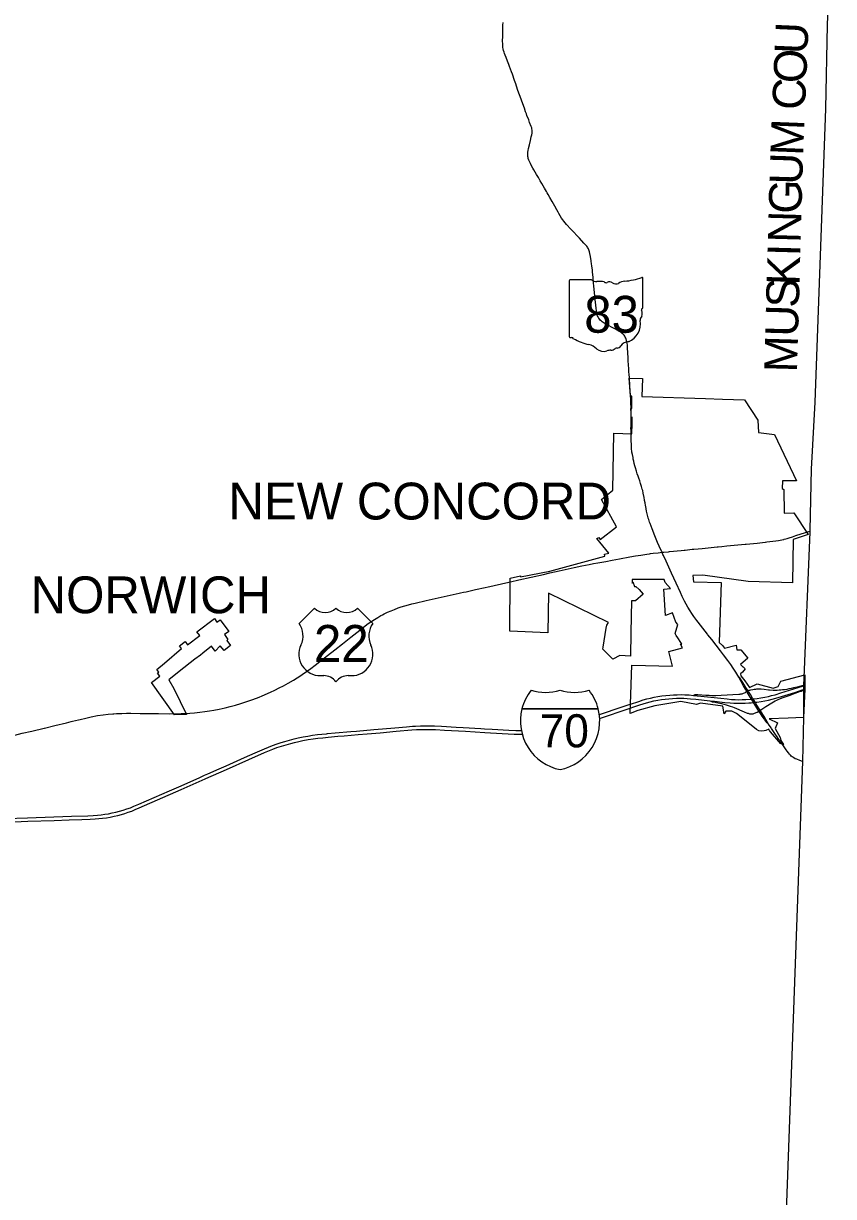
# Model space of a CAD drawing. Extents: x 2015843 to 2287843, y 623733 to 799733.
# Drawn here: x 2176633 to 2201296, y 702171 to 737859 of the extents above; entities that cross this region are included whole.
import ezdxf

# ---------------------------------------------------------------- set-up
doc = ezdxf.new("R2010")
doc.units = 0
for name, color, linetype in [('GM_X_Corporation', 7, 'Continuous'), ('GM_X_Corporation_Text', 7, 'Continuous'), ('GM_X_County', 7, 'Continuous'), ('GM_X_County_Text', 7, 'Continuous'), ('GM_X_Interstate_Location', 7, 'Continuous'), ('GM_X_Interstate_Shield', 7, 'Continuous'), ('GM_X_State_Location', 7, 'Continuous'), ('GM_X_State_Route', 7, 'Continuous'), ('GM_X_State_Shield', 7, 'Continuous'), ('GM_X_US_Location', 7, 'Continuous'), ('GM_X_US_Route', 7, 'Continuous'), ('GM_X_US_Shield', 7, 'Continuous'), ('UT_P_Electric', 7, 'Continuous')]:
    doc.layers.add(name, color=color, linetype=linetype)

msp = doc.modelspace()

# ---------------------------------------------------------------- linework, layer by layer
at = {"layer": 'GM_X_Corporation'}
for points in [[(2191451, 720987), (2191762, 721058), (2191762, 721027), (2192653, 721199), (2194328, 721649), (2194320, 721716), (2194451, 721742), (2194092, 722189), (2194145, 722225), (2194194, 722159), (2194685, 722548), (2194232, 723373), (2194577, 723661), (2194610, 725393), (2195151, 725377), (2195160, 725683), (2195160, 725881), (2195131, 725872), (2195131, 726003), (2195128, 726141), (2195158, 726147), (2195151, 726525), (2195115, 726526), (2195078, 727073), (2195482, 727063), (2195463, 726515), (2197399, 726451), (2197917, 726427), (2198585, 726406), (2198993, 725793), (2199006, 725418), (2199494, 725355), (2200168, 723940), (2199738, 723944), (2199736, 723714), (2199777, 723686), (2199793, 722961), (2200091, 722968), (2200524, 722309), (2200068, 722158), (2200042, 720846), (2198692, 720884), (2197317, 721070), (2197014, 721065), (2197034, 720876), (2197874, 720847), (2197844, 719945), (2197813, 719023), (2197913, 718936), (2197978, 718850), (2198329, 718949), (2198354, 718807), (2198473, 718808), (2198682, 718553), (2198465, 718356), (2198535, 718281), (2198543, 718289), (2198608, 718223), (2198526, 718126), (2198459, 718077), (2198472, 718010), (2198599, 717860), (2198732, 717653), (2198966, 717771), (2199456, 717636), (2199614, 717690), (2199695, 717849), (2200426, 718042), (2200422, 717725), (2200419, 717611), (2200385, 716743), (2199911, 716726), (2199334, 716706), (2199594, 716584), (2199517, 716406), (2199666, 716134), (2199693, 716043), (2199772, 715928), (2199748, 715912), (2199716, 715959), (2199687, 715946), (2199371, 716308), (2199350, 716344), (2199321, 716385), (2199234, 716349), (2199180, 716335), (2199115, 716328), (2199023, 716335), (2198952, 716375), (2198783, 716516), (2198341, 716868), (2198195, 716934), (2198021, 716934), (2197966, 716859), (2197925, 717087), (2197246, 717178), (2197125, 717140), (2196651, 717235), (2195856, 717098), (2195333, 716961), (2195106, 716866), (2195116, 717154), (2195158, 718339), (2196397, 718311), (2196276, 718752), (2196701, 718866), (2196639, 718972), (2196673, 718976), (2196648, 719025), (2196556, 719171), (2196505, 719239), (2196470, 719303), (2196550, 719570), (2196495, 719644), (2196392, 719925), (2196180, 719848), (2196124, 720653), (2196328, 720668), (2196171, 720856), (2196142, 720944), (2195168, 720942), (2195166, 720836), (2195189, 720871), (2195240, 720729), (2195272, 720731), (2195374, 720641), (2195497, 720494), (2195261, 720290), (2195147, 720294), (2195128, 719333), (2195109, 718606), (2194793, 718629), (2194572, 718517), (2194269, 718821), (2194283, 718884), (2194369, 719462), (2194398, 719550), (2194442, 719633), (2192618, 720528), (2192594, 719325), (2191441, 719368)], [(2180536, 717807), (2180787, 718002), (2180715, 718095), (2180755, 718125), (2180698, 718202), (2180922, 718401), (2181445, 718839), (2181383, 718927), (2181552, 719053), (2181630, 718960), (2181998, 719238), (2181914, 719352), (2182449, 719752), (2182522, 719647), (2182625, 719716), (2182890, 719366), (2182751, 719266), (2182859, 719118), (2182821, 719089), (2182936, 718935), (2182740, 718778), (2182622, 718928), (2182467, 718766), (2182355, 718914), (2182098, 718701), (2182018, 718642), (2181854, 718524), (2181374, 718148), (2181054, 717890), (2181214, 717626), (2181601, 716835), (2181232, 716830)]]:
    msp.add_lwpolyline(points, close=True, dxfattribs=at)
at = {"layer": 'GM_X_County'}
msp.add_lwpolyline([(2201296, 742683), (2201102, 737817), (2201047, 735259), (2200727, 726337), (2200609, 724295), (2200576, 722439), (2200575, 722396), (2200380, 717712), (2200376, 717595), (2200385, 716743), (2200352, 715403), (2199774, 699473)], dxfattribs=at)
at = {"layer": 'GM_X_Interstate_Shield'}
for p, q in [((2191808, 717007), (2194131, 717007)), ((2194131, 717007), (2191808, 717007)), ((2194131, 717007), (2191808, 717007))]:
    msp.add_line(p, q, dxfattribs=at)
for centre, start, end in [((2193272, 716637), 141.669, 165.8066), ((2192529, 719016), 253.0091, 286.9909), ((2193411, 719016), 253.0091, 286.9909), ((2192668, 716637), 14.1934, 38.331), ((2193272, 716637), 165.8066, 258.463), ((2192668, 716637), 281.537, 14.1934)]:
    msp.add_arc(centre, 1509, start, end, dxfattribs=at)
at = {"layer": 'GM_X_State_Route'}
msp.add_line((2195135, 725818), (2195136, 725870), dxfattribs=at)
for points in [[(2195030, 727819), (2195029, 727840), (2195023, 727987), (2195021, 728016), (2195018, 728069), (2195011, 728134), (2195006, 728166), (2194995, 728213), (2194980, 728260), (2194968, 728290), (2194954, 728319), (2194937, 728347), (2194918, 728373), (2194897, 728397), (2194873, 728419), (2194836, 728450), (2194795, 728477), (2194725, 728519), (2194619, 728575), (2194595, 728588), (2194406, 728688), (2194335, 728728), (2194279, 728763), (2194252, 728782), (2194226, 728803), (2194202, 728826), (2194180, 728851), (2194170, 728864), (2194151, 728891), (2194142, 728905), (2194126, 728934), (2194113, 728965), (2194103, 728996), (2194094, 729028), (2194087, 729060), (2194078, 729108), (2194076, 729124), (2194069, 729189), (2194057, 729302), (2194049, 729367), (2193998, 729872), (2193990, 729969), (2193977, 730116), (2193966, 730230), (2193961, 730279), (2193952, 730360), (2193937, 730473), (2193933, 730500), (2193928, 730538), (2193914, 730636), (2193896, 730766), (2193880, 730862), (2193869, 730910), (2193860, 730941), (2193849, 730972), (2193835, 731001), (2193819, 731029), (2193802, 731056), (2193782, 731082), (2193762, 731107), (2193696, 731180), (2193561, 731324), (2193506, 731383), (2193359, 731538), (2193302, 731597), (2193169, 731742), (2193126, 731791), (2193084, 731842), (2193054, 731881), (2193017, 731935), (2192974, 732005), (2192933, 732076), (2192909, 732119), (2192869, 732190), (2192806, 732304), (2192726, 732447), (2192661, 732561), (2192604, 732660), (2192579, 732703), (2192555, 732745), (2192498, 732844), (2192417, 732986), (2192368, 733071), (2192310, 733170), (2192252, 733269), (2192169, 733409), (2192144, 733452), (2192104, 733523), (2192065, 733595), (2192037, 733655), (2192018, 733700), (2192002, 733747), (2191994, 733780), (2191989, 733812), (2191987, 733846), (2191988, 733895), (2191992, 733944), (2191998, 733993), (2192011, 734058), (2192036, 734170), (2192067, 734298), (2192094, 734409), (2192109, 734473), (2192117, 734521), (2192121, 734553), (2192122, 734586), (2192120, 734618), (2192115, 734650), (2192107, 734681), (2192091, 734727), (2192043, 734849), (2192014, 734926), (2191961, 735063), (2191943, 735109), (2191920, 735170), (2191882, 735278), (2191832, 735417), (2191755, 735633), (2191716, 735741), (2191678, 735849), (2191619, 736020), (2191582, 736128), (2191517, 736314), (2191489, 736391), (2191434, 736545), (2191412, 736606), (2191372, 736714), (2191329, 736820), (2191297, 736896), (2191279, 736942), (2191264, 736988), (2191250, 737036), (2191239, 737084), (2191231, 737133), (2191225, 737182), (2191223, 737231), (2191222, 737330), (2191224, 737461), (2191224, 737526), (2191224, 737640), (2191226, 737722), (2191229, 737803), (2191235, 737885)], [(2195068, 727239), (2195060, 727350), (2195045, 727595), (2195041, 727660), (2195038, 727709), (2195030, 727819)], [(2195134, 726133), (2195127, 726346), (2195120, 726461), (2195117, 726506), (2195116, 726523), (2195114, 726557), (2195105, 726680), (2195094, 726844), (2195079, 727070), (2195070, 727202), (2195068, 727239)], [(2195136, 725870), (2195136, 726002), (2195134, 726133)], [(2195130, 725391), (2195130, 725423), (2195130, 725480), (2195129, 725545), (2195130, 725593), (2195132, 725691), (2195133, 725723), (2195135, 725818)], [(2195264, 724343), (2195248, 724396), (2195226, 724475), (2195211, 724539), (2195199, 724604), (2195190, 724652), (2195171, 724748), (2195158, 724813), (2195154, 724845), (2195148, 724910), (2195146, 724942), (2195141, 725057), (2195137, 725155), (2195133, 725237), (2195130, 725381), (2195130, 725391)], [(2196079, 721770), (2196065, 721796), (2196021, 721886), (2195985, 721958), (2195940, 722064), (2195878, 722216), (2195853, 722276), (2195773, 722489), (2195712, 722642), (2195695, 722688), (2195667, 722765), (2195651, 722812), (2195649, 722819), (2195637, 722860), (2195619, 722940), (2195610, 722982), (2195602, 723020), (2195577, 723159), (2195572, 723182), (2195570, 723198), (2195556, 723278), (2195543, 723345), (2195541, 723359), (2195526, 723440), (2195503, 723568), (2195485, 723648), (2195472, 723695), (2195450, 723774), (2195421, 723867), (2195396, 723945), (2195370, 724022), (2195348, 724084), (2195321, 724161), (2195295, 724239), (2195264, 724343)], [(2197176, 719642), (2197134, 719697), (2197046, 719816), (2196980, 719910), (2196927, 719993), (2196859, 720105), (2196810, 720191), (2196759, 720288), (2196749, 720307), (2196691, 720425), (2196635, 720543), (2196504, 720827), (2196360, 721140), (2196196, 721498), (2196114, 721677), (2196103, 721703), (2196079, 721770)], [(2198414, 717976), (2198320, 718124), (2198240, 718248), (2198166, 718357), (2198079, 718477), (2197950, 718647), (2197850, 718777), (2197718, 718945), (2197587, 719114), (2197471, 719262), (2197456, 719281), (2197385, 719372), (2197176, 719642)], [(2198916, 717193), (2198907, 717206), (2198845, 717308), (2198832, 717328), (2198763, 717440), (2198703, 717538), (2198694, 717553), (2198630, 717656), (2198535, 717806), (2198493, 717869), (2198461, 717918), (2198454, 717930), (2198439, 717950), (2198414, 717976)], [(2199316, 716541), (2199277, 716585), (2199201, 716675), (2199189, 716692), (2199124, 716781), (2199068, 716863), (2199029, 716924), (2199020, 716938), (2198929, 717087), (2198862, 717201), (2198854, 717215), (2198819, 717271), (2198799, 717304), (2198793, 717313), (2198757, 717368), (2198665, 717519), (2198656, 717534), (2198611, 717609), (2198549, 717712), (2198478, 717837), (2198442, 717909), (2198431, 717933), (2198414, 717976)], [(2199316, 716541), (2199235, 716687), (2199181, 716773), (2199071, 716945), (2199059, 716963), (2199031, 717007), (2198927, 717175), (2198916, 717193)], [(2199598, 716129), (2199492, 716284), (2199403, 716413), (2199395, 716426), (2199316, 716541)], [(2199659, 716040), (2199644, 716063), (2199604, 716120), (2199598, 716129)], [(2199690, 715995), (2199684, 716004), (2199659, 716040)], [(2200354, 715401), (2200265, 715436), (2200173, 715472), (2200129, 715492), (2200086, 715515), (2200058, 715533), (2200032, 715552), (2200007, 715573), (2199984, 715595), (2199951, 715631), (2199920, 715669), (2199881, 715722), (2199851, 715764), (2199749, 715910), (2199717, 715956), (2199690, 715995)]]:
    msp.add_lwpolyline(points, dxfattribs=at)
at = {"layer": 'GM_X_State_Shield'}
for p, q in [((2193248, 730032), (2193248, 728331)), ((2193927, 730062), (2193271, 730062)), ((2195490, 729214), (2195490, 730104)), ((2195490, 729214), (2195490, 729214))]:
    msp.add_line(p, q, dxfattribs=at)
for centre, radius, start, end in [((2193274, 730036), 26, 98.1301, 188.1301), ((2194083, 730259), 252, 231.6195, 271.1119), ((2194167, 729107), 904, 80.4867, 94.9883), ((2194372, 730045), 72.7, 219.7921, 297.1024), ((2194479, 729848), 151, 54.4667, 119.1411), ((2194674, 730118), 182, 233.8562, 294.8282), ((2194995, 729542), 478, 97.3462, 120.7689), ((2194691, 732381), 2377, 275.8445, 288.9065), ((2195465, 730108), 25, 351.8621, 97.738), ((2195484, 729149), 38.6, 107.944, 210.337), ((2195238, 729036), 232, 340.033, 23.6496), ((2195463, 729211), 26.7, 289.6038, 7.7341), ((2194825, 728728), 595, 292.3089, 8.9858), ((2195579, 728842), 169, 136.8065, 186.9296), ((2193274, 728328), 26.2, 171.9584, 258.3066), ((2193278, 728502), 200, 267.339, 280.6039), ((2193319, 728233), 72.1, 29.7484, 93.2717), ((2194229, 729762), 1716, 240.4129, 257.1985), ((2193718, 727567), 537, 47.1842, 75.836), ((2194663, 728166), 192, 282.8732, 323.2771), ((2195075, 727854), 326, 94.4031, 142.5768), ((2194298, 728225), 341, 230.7004, 286.2918), ((2194495, 727636), 280, 85.6951, 111.2099), ((2194520, 728097), 182, 268.777, 315.5493), ((2194685, 727933), 51.1, 65.7517, 132.6484)]:
    msp.add_arc(centre, radius, start, end, dxfattribs=at)
at = {"layer": 'GM_X_US_Route'}
for p, q in [((2200147, 722279), (2200577, 722416)), ((2200047, 722246), (2200097, 722262)), ((2200097, 722262), (2200147, 722279)), ((2196745, 721836), (2196778, 721839)), ((2197299, 721891), (2197748, 721935)), ((2197748, 721935), (2197781, 721939)), ((2189940, 720533), (2190034, 720554)), ((2181499, 716865), (2181561, 716867))]:
    msp.add_line(p, q, dxfattribs=at)
for points in [[(2198047, 721964), (2198609, 722019), (2198638, 722021)], [(2198638, 722021), (2198967, 722053), (2199212, 722080), (2199226, 722081)], [(2199226, 722081), (2199261, 722085), (2199357, 722095), (2199537, 722116), (2199622, 722128), (2199724, 722147), (2199780, 722161), (2199794, 722165)], [(2199794, 722165), (2199845, 722180), (2199880, 722191), (2199948, 722212), (2200047, 722246)], [(2194778, 721571), (2195091, 721628), (2195264, 721659), (2195433, 721688), (2195615, 721717), (2195689, 721728), (2195721, 721732)], [(2195721, 721732), (2195806, 721742), (2195954, 721758), (2196079, 721770)], [(2196079, 721770), (2196132, 721775), (2196273, 721788), (2196302, 721791)], [(2196302, 721791), (2196653, 721826), (2196745, 721836)], [(2196778, 721839), (2196996, 721861), (2197044, 721865)], [(2197044, 721865), (2197175, 721879), (2197299, 721891)], [(2197781, 721939), (2197893, 721950), (2198047, 721964)], [(2192663, 721141), (2192947, 721205), (2193396, 721305), (2193630, 721357), (2193855, 721402), (2193991, 721428), (2194124, 721453), (2194363, 721495)], [(2194363, 721495), (2194558, 721530), (2194778, 721571)], [(2191461, 720873), (2191713, 720930), (2192466, 721097), (2192663, 721141)], [(2190034, 720554), (2190110, 720571), (2190398, 720635), (2190446, 720646)], [(2190446, 720646), (2190830, 720733), (2191317, 720840), (2191461, 720873)], [(2187560, 719866), (2187618, 719896), (2187721, 719945), (2187825, 719992), (2187931, 720035), (2188038, 720076), (2188130, 720108), (2188244, 720143), (2188351, 720173), (2188452, 720199), (2188554, 720223), (2188892, 720299), (2189165, 720360), (2189901, 720524), (2189940, 720533)], [(2185103, 718043), (2185114, 718050), (2185250, 718143), (2185384, 718239), (2185516, 718337), (2185710, 718489), (2185890, 718632), (2186109, 718805), (2186341, 718988), (2186598, 719191), (2186869, 719405), (2187037, 719535), (2187129, 719602), (2187237, 719676), (2187319, 719729), (2187417, 719788), (2187516, 719843), (2187560, 719866)], [(2183828, 717374), (2183881, 717395), (2183988, 717440), (2184153, 717514), (2184287, 717577), (2184419, 717643), (2184550, 717712), (2184694, 717792), (2184851, 717883), (2184963, 717952), (2185103, 718043)], [(2181561, 716867), (2181592, 716868), (2181702, 716877), (2181844, 716891), (2182007, 716909), (2182154, 716928), (2182300, 716950), (2182430, 716972), (2182592, 717003), (2182769, 717042), (2182929, 717080), (2183088, 717123), (2183246, 717169), (2183403, 717219), (2183558, 717272), (2183759, 717347), (2183828, 717374)], [(2178089, 716619), (2178128, 716628), (2178310, 716674)], [(2178310, 716674), (2178357, 716685), (2178530, 716728), (2178692, 716764), (2178887, 716801), (2179056, 716825), (2179212, 716842), (2179354, 716855)], [(2179354, 716855), (2179382, 716857), (2179464, 716863), (2179628, 716870), (2179775, 716874), (2179907, 716873), (2180187, 716870), (2180467, 716867), (2180747, 716864), (2181086, 716860), (2181192, 716862)], [(2181192, 716862), (2181214, 716862), (2181298, 716861), (2181437, 716862), (2181499, 716865)], [(2176010, 716123), (2176136, 716153), (2176375, 716209), (2176598, 716263), (2176885, 716331), (2177261, 716419), (2177269, 716421)], [(2177269, 716421), (2177593, 716499), (2177947, 716584), (2178089, 716619)]]:
    msp.add_lwpolyline(points, dxfattribs=at)
at = {"layer": 'GM_X_US_Shield'}
for p, q in [((2185493, 720073), (2185026, 719606)), ((2187268, 719606), (2186801, 720073)), ((2185680, 718018), (2185774, 718018)), ((2186521, 718018), (2186614, 718018))]:
    msp.add_line(p, q, dxfattribs=at)
for centre, radius, start, end in [((2185820, 720406), 467, 225.573, 314.427), ((2186474, 720406), 467, 225.573, 314.427), ((2184491, 719231), 654, 334.5471, 35.0009), ((2187803, 719231), 654, 144.9991, 205.4529), ((2185673, 718672), 654, 154.8319, 270.6383), ((2186621, 718672), 654, 269.3617, 25.1681), ((2185774, 717551), 467, 36.8699, 90), ((2186521, 717551), 467, 90, 143.1301)]:
    msp.add_arc(centre, radius, start, end, dxfattribs=at)
at = {"layer": 'UT_P_Electric'}
for points in [[(2197035, 717418), (2197044, 717417), (2197354, 717385), (2197859, 717329), (2198055, 717308), (2198186, 717297), (2198301, 717291), (2198416, 717287), (2198514, 717288), (2198629, 717292), (2198760, 717300), (2198799, 717304), (2198845, 717308), (2198859, 717309), (2198973, 717323), (2199086, 717340), (2199199, 717361), (2199312, 717385), (2199408, 717409), (2199518, 717439), (2199691, 717492), (2200351, 717700), (2200381, 717709)], [(2200381, 717709), (2200327, 717706), (2200302, 717702), (2200183, 717672), (2200078, 717644), (2200004, 717625), (2199933, 717612), (2199870, 717600), (2199803, 717590), (2199741, 717582), (2199689, 717577), (2199636, 717573), (2199574, 717570), (2199487, 717569), (2199459, 717569), (2199344, 717576), (2199319, 717579), (2199186, 717592), (2199090, 717602), (2199046, 717604), (2198999, 717604), (2198954, 717602), (2198917, 717600), (2198881, 717596), (2198836, 717589), (2198763, 717575), (2198741, 717569), (2198716, 717561), (2198694, 717553)], [(2194165, 716830), (2194167, 716831), (2194860, 717065), (2195069, 717135), (2195112, 717150), (2195117, 717152), (2195363, 717234), (2195504, 717277), (2195615, 717308), (2195726, 717336), (2195838, 717361), (2195951, 717382), (2196064, 717400), (2196194, 717416), (2196308, 717427), (2196422, 717435), (2196537, 717439), (2196652, 717440), (2196766, 717437), (2196897, 717430), (2197035, 717418)], [(2198694, 717553), (2198656, 717534), (2198627, 717516), (2198601, 717500), (2198575, 717486), (2198548, 717473), (2198527, 717465), (2198505, 717458), (2198487, 717454), (2198466, 717450), (2198442, 717447), (2198414, 717444), (2197872, 717413), (2197708, 717404), (2197646, 717404), (2197576, 717405), (2197504, 717409), (2197412, 717414), (2197165, 717434), (2197097, 717437), (2197075, 717433), (2197035, 717418)], [(2198784, 717194), (2198831, 717198), (2198862, 717201), (2198907, 717206), (2198961, 717212), (2199091, 717230), (2199204, 717249), (2199316, 717272), (2199427, 717298), (2199538, 717328), (2199711, 717380), (2200117, 717508), (2200344, 717582), (2200377, 717592)], [(2199059, 716963), (2199110, 717000), (2199235, 717079), (2199416, 717191), (2199516, 717247), (2199566, 717272), (2199605, 717290), (2199663, 717314), (2199727, 717339), (2199796, 717365), (2199975, 717425), (2200049, 717453), (2200292, 717541), (2200315, 717550), (2200336, 717560), (2200377, 717592)], [(2194175, 716718), (2195073, 717021), (2195133, 717042)], [(2195133, 717042), (2195183, 717059), (2195272, 717089), (2195396, 717130), (2195605, 717193), (2195716, 717222), (2195828, 717247), (2195941, 717269), (2196055, 717288), (2196168, 717303), (2196283, 717315), (2196397, 717323), (2196512, 717328), (2196627, 717330), (2196742, 717328), (2196840, 717324), (2196938, 717317), (2197101, 717302), (2197533, 717255), (2197672, 717239), (2197981, 717205), (2198144, 717190), (2198259, 717183), (2198373, 717179), (2198488, 717179), (2198602, 717182), (2198717, 717189), (2198784, 717194)], [(2197533, 717255), (2197578, 717229), (2197598, 717223), (2197643, 717217), (2197737, 717202), (2197882, 717170), (2197951, 717152), (2198025, 717133), (2198088, 717113), (2198150, 717092), (2198215, 717069), (2198273, 717045), (2198576, 716916), (2198668, 716880), (2198692, 716872), (2198715, 716865), (2198735, 716861), (2198763, 716857), (2198786, 716855), (2198812, 716856), (2198829, 716857), (2198845, 716860), (2198867, 716865), (2198893, 716873), (2198919, 716884), (2198938, 716893), (2198969, 716910), (2199020, 716938), (2199059, 716963)], [(2176096, 713672), (2176752, 713695), (2178096, 713739), (2178588, 713755), (2178752, 713763), (2178883, 713773), (2178997, 713784), (2179111, 713799), (2179225, 713818), (2179337, 713840), (2179450, 713866), (2179561, 713894), (2179671, 713926), (2179781, 713962), (2179889, 714001), (2179996, 714043), (2180147, 714107), (2181077, 714518), (2181364, 714639), (2181620, 714750), (2181815, 714836), (2181980, 714910), (2182129, 714979), (2182145, 714986), (2182248, 715033), (2182593, 715186), (2182803, 715279), (2183028, 715379), (2183358, 715524), (2183688, 715670), (2183973, 715795), (2184094, 715846), (2184216, 715893), (2184355, 715943), (2184479, 715985), (2184589, 716019), (2184731, 716059), (2184874, 716096), (2185001, 716126), (2185146, 716155), (2185291, 716181), (2185437, 716204), (2185583, 716223), (2185714, 716237), (2185855, 716252), (2185893, 716256), (2186122, 716277), (2186596, 716318), (2186775, 716333), (2187298, 716378), (2187560, 716401), (2187936, 716434), (2188295, 716465), (2188475, 716479), (2188573, 716485), (2188721, 716492), (2188868, 716495), (2188999, 716494), (2189147, 716490), (2189360, 716479), (2189802, 716453), (2190015, 716441), (2190555, 716409), (2190670, 716403), (2190899, 716390), (2191407, 716361), (2191620, 716351), (2191751, 716348), (2191790, 716348)], [(2176357, 713572), (2176767, 713586), (2177570, 713612), (2178029, 713627), (2178406, 713640), (2178668, 713649), (2178816, 713657), (2178930, 713667), (2179044, 713680), (2179157, 713696), (2179270, 713715), (2179399, 713741), (2179510, 713768), (2179621, 713797), (2179715, 713826), (2179824, 713862), (2179932, 713900), (2180039, 713942), (2180160, 713993), (2181435, 714557), (2182169, 714882), (2182187, 714890), (2182815, 715166), (2183490, 715465), (2183970, 715677), (2184121, 715740), (2184228, 715782), (2184351, 715828), (2184491, 715875), (2184633, 715918), (2184775, 715958), (2184886, 715988), (2185014, 716017), (2185142, 716044), (2185304, 716074), (2185450, 716097), (2185596, 716116), (2185743, 716131), (2185905, 716147), (2186200, 716175), (2186396, 716191), (2186822, 716224), (2187099, 716248), (2187492, 716282), (2187982, 716326), (2188456, 716366), (2188603, 716376), (2188734, 716381), (2188882, 716384), (2189030, 716382), (2189177, 716377), (2189456, 716362), (2190095, 716326), (2190684, 716292), (2191208, 716262), (2191568, 716242), (2191700, 716238), (2191816, 716237)]]:
    msp.add_lwpolyline(points, dxfattribs=at)

# ---------------------------------------------------------------- texts
at = {"layer": 'GM_X_Corporation_Text'}
for s, p in [('NEW CONCORD', (2182872, 722769)), ('NORWICH', (2176850, 719916))]:
    msp.add_text(s, height=1120, rotation=0, dxfattribs=at).set_placement(p)
at = {"layer": 'GM_X_County_Text'}
for s, rotation, p in [('U', 87.501, (2200497, 736910)), ('O', 87.4982, (2200459, 736026)), ('C', 87.5111, (2200424, 735213)), ('M', 87.8244, (2200369, 733825)), ('U', 88.175, (2200341, 732943)), ('G', 88.3839, (2200316, 732060)), ('N', 88.4037, (2200292, 731176)), ('I', 88.4017, (2200280, 730767)), ('K', 88.4035, (2200256, 729883)), ('S', 88.4017, (2200237, 729205)), ('U', 88.4037, (2200212, 728321)), ('M', 88.4017, (2200182, 727235))]:
    msp.add_text(s, height=1000, rotation=rotation, dxfattribs=at).set_placement(p)
at = {"layer": 'GM_X_Interstate_Location'}
msp.add_text('70', height=1, rotation=0, dxfattribs=at).set_placement((2196799, 717108))
for s in ['.', '-', ',']:
    msp.add_text(s, height=1, dxfattribs=at).set_placement((2197003, 717315))
at = {"layer": 'GM_X_Interstate_Shield'}
msp.add_text('70', height=1006.2, dxfattribs=at).set_placement((2192351, 715837))
at = {"layer": 'GM_X_State_Location'}
for s in ['s', 'r']:
    msp.add_text(s, height=1, dxfattribs=at).set_placement((2193979, 728766))
msp.add_text('83', height=1, rotation=0, dxfattribs=at).set_placement((2193728, 728693))
at = {"layer": 'GM_X_State_Shield'}
msp.add_text('83', height=1120.7, dxfattribs=at).set_placement((2193705, 728451))
at = {"layer": 'GM_X_US_Location'}
msp.add_text('22', height=1, rotation=0, dxfattribs=at).set_placement((2185799, 718415))
for s in ['0', '/']:
    msp.add_text(s, height=1, dxfattribs=at).set_placement((2186005, 718622))
at = {"layer": 'GM_X_US_Shield'}
msp.add_text('22', height=1120.7, dxfattribs=at).set_placement((2185477, 718438))

doc.saveas('drawing.dxf')
